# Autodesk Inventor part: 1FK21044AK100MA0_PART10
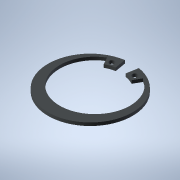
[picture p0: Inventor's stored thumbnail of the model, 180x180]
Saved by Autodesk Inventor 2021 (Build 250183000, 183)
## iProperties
Created: 2025-04
Part Number: 1FK21044AK100MA0_PART10
Material: Generic
Catalog Web Link: www.3dfindit.com
Description: -Servo synchronous motor
Document SubType Name: Modeling
Designer: psAdmin
Mass: 0.642463 g
Surface Area: 12.3927 cm^2
Volume: 0.642463 cm^3
Density: 1 g/cm^3
Appearance: PSOLRGB-212-217-219
Category: PARTsolutions
Title: 1FK21044AK100MA0_PART10
Author: Cadenas PARTsolutions
Comments: Servo synchronous motor
Sending System: PARTsolutions
Preprocessor: ST-DEVELOPER v19.3
PSOL_IDENT_0: {$CADENAS_DATA/23d-libs/siemens_ag/_cat_/5e/d8/1fk21044ak100ma0.prj},216 {VTYP=3D},{NB=1FK21044AK100
PSOL_IDENT_1: MA0_PART10},{LINA=1FK21044AK100MA0_PART10},{NN=1FK21044AK100MA0_PART10},{NOPRJ=TRUE},{DATE=19.08.202
PSOL_IDENT_2: 5 14:00:41},{GEOMDATE=30.07.2025 02:00:53},{VERSION=},{LINEID=10},{WBVAR=},{WBNUMERIC=}  {NB=1FK2104
PSOL_IDENT_3: 4AK100MA0_PART10},{LINA=1FK21044AK100MA0_PART10},{KT=DUMMY},{PREVIEW=../../../_pool_/cb/72/p_d211_xx
PSOL_IDENT_4: _00434j.png},{DESCSHORT=SIMOTICS S-1FK2 HD, SINAMICS S210 3AC 400V-480V, 0.95 Nm, 6000 rpm},{DESCLON
PSOL_IDENT_5: G=SIMOTICS S-1FK2 HD servo motor M0=1.27 Nm; PN = 0.6 kW at nN=6000 rpm (380-480 V); PN = 0.4 kW at
PSOL_IDENT_6: nN=3000 rpm (200-240 V); with holding brake; degree of protection IP64; cylindrical shaft D19x40mm;
PSOL_IDENT_7: absolute encoder 22-bit + 12-bit multiturn (encoder AM22DQC); with OCC interface; plug size M17, rot
PSOL_IDENT_8: atable; SIMOTICS S-1FK2 servomotorfor a wide range of uses in industrial environments. SIMOTICS S‑1F
PSOL_IDENT_9: K2 servomotors are compact synchronous motors with a high dynamic performance that set themselves ap
PSOL_IDENT_10: art as a result of their high power density, degree of protection and overload capability. The motor
PSOL_IDENT_11: s are available in two variants: as High Dynamic variant (highest dynamic performance as a result of
PSOL_IDENT_12: the low intrinsic moment of inertia for applications demanding a high dynamic performance with low
PSOL_IDENT_13: moved masses) - and as Compact variant (precise and stable closed-loop control for medium up to larg
PSOL_IDENT_14: e moved masses as a result of a medium intrinsic moment of inertia). SIMOTICSS‑1FK2 servomotors full
PSOL_IDENT_15: y exploit their strengths in a system with the SINAMICSS210 frequency converter and simple connectio
PSOL_IDENT_16: n using the one cable connection (OCC). Advantages include the short control and positioning times,
PSOL_IDENT_17: fast and precise correction of disturbing quantities as well as stable control with a high dynamic p
PSOL_IDENT_18: erformance. The servo motors can be configured to address a wide range of requirements. For example
PSOL_IDENT_19: with and without holding brake, IP64 or IP65 degree of protection, singleturn or multiturn absolute
PSOL_IDENT_20: encoders - to name just a few. Further, the servomotors are available in different shaft heights ext
PSOL_IDENT_21: ending from 20 to 100. A shaft sealing ring is available to achieve an IP65 degree of protection and
PSOL_IDENT_22: for subsequent mounting at the motor or as spare part. SIMOTICS - the optimum motor for each and ev
PSOL_IDENT_23: ery motion control application.},{INTNO=804766910005},{SUPPLIERALTNO=1FK2104-4AK10-0MA0},{MANUID=1FK
PSOL_IDENT_24: 21044AK100MA0},{MANUNAME=Siemens},{MANUTYPEDESC=Synchronous motor 1FK2-HD 1,27 Nm},{AAU732=SIMOTICS}
PSOL_IDENT_25: ,{AAO057=S-1FK2},{AAU734=SIMOTICS S-1FK2 HD servo motor M0=1.27 Nm; PN = 0.6 kW at nN=6000 rpm (380-
PSOL_IDENT_26: 480 V); PN = 0.4 kW at nN=3000 rpm (200-240 V); with holding brake; degree of protection IP64; cylin
PSOL_IDENT_27: drical shaft D19x40mm; absolute encoder 22-bit + 12-bit multiturn (encoder AM22DQC); with OCC interf
PSOL_IDENT_28: ace; plug size M17, rotatable;},{AAW338=Synchronous motor 1FK2-HD 1,27 Nm},{AAO742=SIMOTICS},{AAO663=
PSOL_IDENT_29: 4042948691076},{NOCUPEROU=1},{PRICEQUANTITY=1},{QUANTITYMIN=1},{QUANTITYINT=1},{CTN=85015100},{COO=D
PSOL_IDENT_30: E},{AAO676=1FK2104-4AK10-0MA0},{AAO677=Siemens AG},{ORDERUNIT=C62},{CONTENTUNIT=C62}
NB: 1FK21044AK100MA0_PART10
NT: Servo synchronous motor
NBSYN: $MANUID._PART10
LINA: 1FK21044AK100MA0_PART10
CATALOG: SIEMENS
PREVIEW: ../../../_pool_/cb/72/p_d211_xx_00434j.png
DESCSHORT: SIMOTICS S-1FK2 HD, SINAMICS S210 3AC 400V-480V, 0.95 Nm, 6000 rpm
DESCLONG: SIMOTICS S-1FK2 HD servo motor M0=1.27 Nm; PN = 0.6 kW at nN=6000 rpm (380-480 V); PN = 0.4 kW at nN=3000 rpm (200-240 V); with holding brake; degree of protect
INTNO: 804766910005
SUPPLIERALTNO: 1FK2104-4AK10-0MA0
MANUID: 1FK21044AK100MA0
MANUNAME: Siemens
MANUTYPEDESC: Synchronous motor 1FK2-HD 1,27 Nm
AAU732: SIMOTICS
AAO057: S-1FK2
AAU734: SIMOTICS S-1FK2 HD servo motor M0=1.27 Nm; PN = 0.6 kW at nN=6000 rpm (380-480 V); PN = 0.4 kW at nN=3000 rpm (200-240 V); with holding brake; degree of protect
AAW338: Synchronous motor 1FK2-HD 1,27 Nm
AAO742: SIMOTICS
AAO663: 4042948691076.0
NOCUPEROU: 1
PRICEQUANTITY: 1
QUANTITYMIN: 1
QUANTITYINT: 1
CTN: 85015100
COO: DE
ARTICLENO: 1FK21044AK100MA0_PART10
BOMINFO: 1FK21044AK100MA0_PART10
CREATOR: CADENAS GmbH
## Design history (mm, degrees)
feature "2025_04_17_15_35_41_0968"
body "Solid1"
